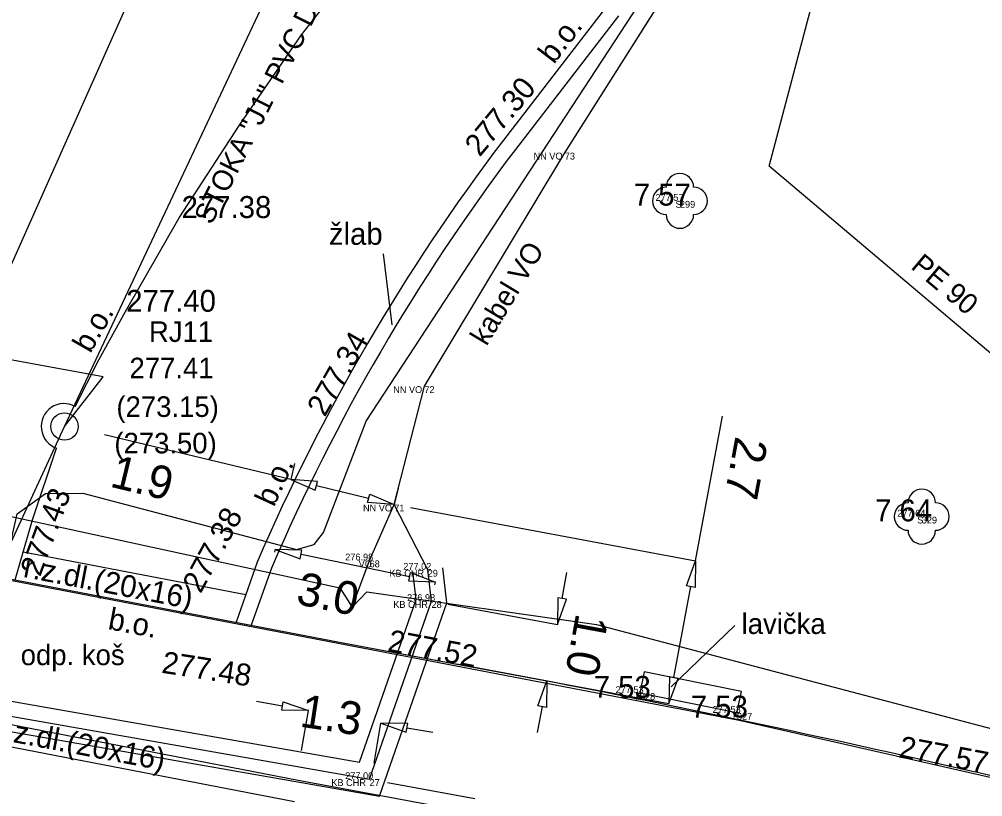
# Model space of a CAD drawing. Extents: x -601602 to -600882, y -1162594 to -1161950.
# Drawn here: x -601194.43 to -601176.86, y -1162080.85 to -1162066.67 of the extents above; entities that cross this region are included whole.
import ezdxf

# ---------------------------------------------------------------- set-up
doc = ezdxf.new("R2010")
doc.units = 0
for name, color, linetype in [('BODY', 7, 'Continuous'), ('BODY_CISLA', 7, 'Continuous'), ('BODY_KODY', 7, 'Continuous'), ('BODY_VYSKY_CELE', 7, 'Continuous'), ('G_POLOHOPIS', 7, 'Continuous'), ('G_TEXTY', 7, 'Continuous'), ('G_ZELEN', 7, 'Continuous'), ('G_ZNACKY', 7, 'Continuous'), ('H_KOTY_VYSKOVE', 7, 'Continuous'), ('H_VYSKY_PREVZATE', 7, 'Continuous'), ('IS_CHRÁNIČKY', 7, 'Continuous'), ('IS_EON_NN', 7, 'Continuous'), ('IS_KAN_JEDNOTNA', 7, 'Continuous'), ('IS_KAN_SPLASKOVA', 7, 'Continuous'), ('IS_PLYNOVOD', 7, 'Continuous'), ('IS_VO', 7, 'Continuous'), ('IS_VO_AREAL', 7, 'Continuous'), ('IS_VODOVOD', 7, 'Continuous'), ('KN_Hranice parcel', 7, 'Continuous'), ('VRSTVA 40', 7, 'Continuous'), ('Vrstva 49', 7, 'Continuous'), ('VRSTVA 5', 7, 'Continuous'), ('Vrstva 7', 7, 'Continuous')]:
    doc.layers.add(name, color=color, linetype=linetype)

# ---------------------------------------------------------------- blocks, each defined once
blk = doc.blocks.new('POINT_DISPLAY')
blk.add_line((0, 0), (0, 0))

msp = doc.modelspace()

# ---------------------------------------------------------------- linework, layer by layer
at = {"layer": 'G_POLOHOPIS'}
for p, q in [((-601183.03, -1162078.57), (-601183.11, -1162078.96)), ((-601181.26, -1162078.93), (-601183.03, -1162078.57)), ((-601181.34, -1162079.32), (-601183.11, -1162078.96)), ((-601181.34, -1162079.32), (-601181.26, -1162078.93))]:
    msp.add_line(p, q, dxfattribs=at)
at = {"layer": 'G_TEXTY'}
msp.add_line((-601181.38, -1162077.727), (-601182.54, -1162078.847), dxfattribs=at)
at = {"layer": 'G_ZELEN'}
for centre in [(-601182.38, -1162069.98), (-601177.97, -1162075.74)]:
    msp.add_circle(centre, 0.00025, dxfattribs=at)
for centre, start, end in [((-601182.38, -1162069.73), 0, 180), ((-601182.63, -1162069.98), 90, 270), ((-601182.13, -1162069.98), 270, 90), ((-601182.38, -1162070.23), 180, 360), ((-601177.97, -1162075.49), 0, 180), ((-601178.22, -1162075.74), 90, 270), ((-601177.72, -1162075.74), 270, 90), ((-601177.97, -1162075.99), 180, 360)]:
    msp.add_arc(centre, 0.25, start, end, dxfattribs=at)
at = {"layer": 'G_ZNACKY'}
msp.add_circle((-601193.603, -1162074.095), 0.25, dxfattribs=at)
at = {"layer": 'IS_CHRÁNIČKY'}
for points in [[(-601269.322, -1162072.054), (-601264.751, -1162067.079), (-601263.901, -1162066.729), (-601260.559, -1162067.068), (-601254.608, -1162068.26), (-601248.108, -1162069.46), (-601239.768, -1162071.15), (-601235.321, -1162071.969), (-601188.223, -1162080.219), (-601187.191, -1162077.25), (-601187.253, -1162076.744)], [(-601268.918, -1162072.426), (-601264.429, -1162067.541), (-601263.819, -1162067.291), (-601260.641, -1162067.612), (-601254.712, -1162068.8), (-601248.212, -1162070), (-601239.872, -1162071.69), (-601235.419, -1162072.511), (-601187.857, -1162080.841), (-601186.629, -1162077.31), (-601186.707, -1162076.676)]]:
    msp.add_lwpolyline(points, dxfattribs=at)
at = {"layer": 'IS_EON_NN'}
msp.add_lwpolyline([(-601195.29, -1162079.33), (-601194.47, -1162075.69), (-601193.95, -1162075.32), (-601193.27, -1162075.31), (-601189.37, -1162076.34), (-601189.05, -1162076.25), (-601188.88, -1162076.03), (-601188.1, -1162074), (-601182.8, -1162065.89), (-601180.73, -1162060), (-601180.49, -1162059.07), (-601180.33, -1162057.81), (-601181.56, -1162053.79), (-601182.34, -1162051.29), (-601183.48, -1162047.77), (-601184.72, -1162041.63), (-601184.91, -1162041.27)], dxfattribs=at)
at = {"layer": 'IS_KAN_JEDNOTNA'}
msp.add_line((-601197.971, -1162083.54), (-601193.603, -1162074.095), dxfattribs=at)
at = {"layer": 'IS_KAN_SPLASKOVA'}
for points in [[(-601193.603, -1162074.095), (-601184.326, -1162054.364)], [(-601193.603, -1162074.095), (-601192.9, -1162073.189), (-601219.294, -1162068.342)]]:
    msp.add_lwpolyline(points, dxfattribs=at)
at = {"layer": 'IS_PLYNOVOD'}
msp.add_lwpolyline([(-601188.62, -1162054.28), (-601187.94, -1162056.22), (-601196.32, -1162075.05)], dxfattribs=at)
at = {"layer": 'IS_VO'}
msp.add_lwpolyline([(-601221, -1162071.19), (-601220.94, -1162070.52), (-601220.15, -1162070.38), (-601205.25, -1162073.42), (-601205.07, -1162074.26), (-601204.715, -1162073.536), (-601188.58, -1162077.04), (-601188.36, -1162077.39), (-601188.09, -1162077.11), (-601183.9, -1162077.71), (-601173.92, -1162080.34), (-601173.63, -1162080.41), (-601159.1, -1162083.69), (-601159.12, -1162084.51), (-601158.666, -1162083.84), (-601145.3, -1162088.52)], dxfattribs=at)
at = {"layer": 'IS_VO_AREAL'}
msp.add_lwpolyline([(-601188.36, -1162077.39), (-601188.04, -1162076.54), (-601187.59, -1162075.52), (-601187.04, -1162073.36), (-601184.48, -1162069.1), (-601182.63, -1162066.18), (-601180.78, -1162062.19), (-601180.2, -1162059.82), (-601180.67, -1162056.17), (-601181.22, -1162052.64), (-601181.8, -1162050.4), (-601183.53, -1162045.99), (-601184.44, -1162042.4), (-601184.75, -1162039.81), (-601184.64, -1162038.31), (-601183.62, -1162036.02), (-601183.14, -1162034.73), (-601183.07, -1162033.56), (-601182.29, -1162031.84)], dxfattribs=at)
at = {"layer": 'IS_VODOVOD'}
msp.add_lwpolyline([(-601173.453, -1162076.323), (-601173.346, -1162075.998), (-601173.532, -1162075.454), (-601180.753, -1162069.349), (-601179.01, -1162062.743), (-601175.747, -1162061.656), (-601172.447, -1162060.451), (-601167.292, -1162058.586), (-601162.43, -1162056.641), (-601160.803, -1162054.849), (-601159.903, -1162053.41), (-601158.77, -1162051.508), (-601157.252, -1162048.634), (-601156.804, -1162047.317), (-601155.861, -1162044.019), (-601155.023, -1162041.098), (-601154.828, -1162039.298), (-601154.638, -1162035.819), (-601155.419, -1162031.331), (-601156.644, -1162026.466), (-601156.968, -1162024.813), (-601159.618, -1162011.435)], dxfattribs=at)
at = {"layer": 'KN_Hranice parcel'}
msp.add_lwpolyline([(-601156.16, -1162086.15), (-601160.29, -1162084.78), (-601165.08, -1162083.36), (-601173.19, -1162081.3), (-601181.3, -1162079.46), (-601222.59, -1162071.53)], dxfattribs=at)
at = {"layer": 'VRSTVA 40'}
for p, q in [((-601182.095, -1162076.544), (-601181.604, -1162073.909)), ((-601189.478, -1162075.064), (-601192.876, -1162074.245)), ((-601189.407, -1162074.773), (-601189.478, -1162075.064)), ((-601188.057, -1162075.407), (-601189.011, -1162075.177)), ((-601187.52, -1162075.228), (-601187.59, -1162075.52)), ((-601187.295, -1162075.575), (-601182.095, -1162076.544)), ((-601189.77, -1162076.386), (-601189.759, -1162076.337)), ((-601187.31, -1162076.84), (-601189.289, -1162076.433)), ((-601184.528, -1162077.234), (-601184.44, -1162076.762)), ((-601186.85, -1162076.986), (-601186.839, -1162076.937)), ((-601182.493, -1162078.678), (-601182.183, -1162077.016)), ((-601186.615, -1162077.335), (-601184.615, -1162077.706)), ((-601187.781, -1162078.181), (-601182.581, -1162079.15)), ((-601186.806, -1162078.363), (-601184.806, -1162078.734)), ((-601189.628, -1162079.196), (-601190.101, -1162079.113)), ((-601189.282, -1162080.008), (-601189.155, -1162079.278)), ((-601184.894, -1162079.206), (-601184.981, -1162079.678)), ((-601187.959, -1162080.239), (-601187.832, -1162079.509)), ((-601187.359, -1162079.592), (-601186.886, -1162079.674)), ((-601187.716, -1162080.589), (-601186.119, -1162080.885))]:
    msp.add_line(p, q, dxfattribs=at)
for points in [[(-601189.03, -1162075.255), (-601188.992, -1162075.099), (-601189.478, -1162075.064)], [(-601188.075, -1162075.485), (-601188.038, -1162075.329), (-601187.59, -1162075.52)], [(-601189.305, -1162076.512), (-601189.273, -1162076.355), (-601189.759, -1162076.337)], [(-601182.104, -1162077.031), (-601182.262, -1162077.001), (-601182.095, -1162076.544)], [(-601187.326, -1162076.919), (-601187.294, -1162076.762), (-601186.839, -1162076.937)], [(-601184.449, -1162077.248), (-601184.606, -1162077.219), (-601184.615, -1162077.706)], [(-601184.815, -1162079.221), (-601184.972, -1162079.191), (-601184.806, -1162078.734)], [(-601182.414, -1162078.693), (-601182.571, -1162078.664), (-601182.581, -1162079.15)], [(-601189.642, -1162079.274), (-601189.614, -1162079.117), (-601189.155, -1162079.278)], [(-601187.372, -1162079.67), (-601187.345, -1162079.513), (-601187.832, -1162079.509)]]:
    msp.add_lwpolyline(points, close=True, dxfattribs=at)
at = {"layer": 'Vrstva 49'}
msp.add_line((-601187.79, -1162070.947), (-601187.633, -1162072.239), dxfattribs=at)
at = {"layer": 'VRSTVA 5'}
for p, q in [((-601184.48, -1162069.1), (-601182.63, -1162066.18)), ((-601187.04, -1162073.36), (-601184.48, -1162069.1)), ((-601235.4, -1162072.236), (-601188.04, -1162080.53)), ((-601187.59, -1162075.52), (-601187.04, -1162073.36)), ((-601186.98, -1162076.71), (-601187.59, -1162075.52)), ((-601186.91, -1162077.28), (-601186.98, -1162076.71)), ((-601188.04, -1162080.53), (-601186.91, -1162077.28))]:
    msp.add_line(p, q, dxfattribs=at)
at = {"layer": 'Vrstva 7'}
for p, q in [((-601189.28, -1162066.95), (-601188.05, -1162065.37)), ((-601183.74, -1162066.46), (-601185.6, -1162068.87)), ((-601183.499, -1162066.603), (-601185.38, -1162069.04)), ((-601190.41, -1162068.6), (-601189.28, -1162066.95)), ((-601191.51, -1162070.29), (-601190.41, -1162068.6)), ((-601192.49, -1162072), (-601191.51, -1162070.29)), ((-601192.98, -1162072.88), (-601192.49, -1162072)), ((-601193.41, -1162073.73), (-601192.98, -1162072.88)), ((-601194.19, -1162075.8), (-601193.75, -1162074.49)), ((-601194.501, -1162076.895), (-601194.19, -1162075.8)), ((-601194.36, -1162076.38), (-601190.298, -1162077.163)), ((-601195.88, -1162076.63), (-601188.59, -1162078.03)), ((-601190.09, -1162076.57), (-601190.475, -1162077.668)), ((-601189.83, -1162076.68), (-601190.202, -1162077.72)), ((-601188.59, -1162078.03), (-601186.45, -1162078.43)), ((-601196.39, -1162079.18), (-601189.34, -1162080.55)), ((-601196.47, -1162079.57), (-601189.41, -1162080.94)), ((-601189.34, -1162080.55), (-601185.58, -1162081.25))]:
    msp.add_line(p, q, dxfattribs=at)
for centre, radius, start, end in [((-601156.293, -1162091.118), 36.795, 142.7959, 156.7097), ((-601156.303, -1162091.092), 36.493, 142.823, 156.7387), ((-601193.611, -1162074.096), 0.418, 61.2022, 250.5933), ((-601224.909, -1162286.548), 211.642, 76.95282, 79.53024), ((-601316.234, -1162688.106), 623.453, 76.572769, 77.107686)]:
    msp.add_arc(centre, radius, start, end, dxfattribs=at)

# ---------------------------------------------------------------- block references
at = {"layer": 'BODY'}
for p in [(-601184.48, -1162069.1), (-601182.38, -1162069.98), (-601187.04, -1162073.36), (-601187.59, -1162075.52), (-601177.97, -1162075.74), (-601188.04, -1162076.54), (-601186.98, -1162076.71), (-601186.91, -1162077.28), (-601183.11, -1162078.96), (-601181.34, -1162079.32), (-601188.04, -1162080.53)]:
    msp.add_blockref('POINT_DISPLAY', p, dxfattribs=at)

# ---------------------------------------------------------------- texts
at = {"layer": 'BODY_CISLA'}
for s, p in [('73', (-601184.48, -1162069.225)), ('299', (-601182.38, -1162070.105)), ('72', (-601187.04, -1162073.485)), ('71', (-601187.59, -1162075.645)), ('329', (-601177.97, -1162075.865)), ('68', (-601188.04, -1162076.665)), ('29', (-601186.98, -1162076.835)), ('28', (-601186.91, -1162077.405)), ('328', (-601183.11, -1162079.085)), ('327', (-601181.34, -1162079.445)), ('27', (-601188.04, -1162080.655))]:
    msp.add_text(s, height=0.125, dxfattribs=at).set_placement(p)
at = {"layer": 'BODY_KODY'}
for s, p in [('NN VO', (-601185.05, -1162069.225)), ('S', (-601182.461, -1162070.105)), ('NN VO', (-601187.61, -1162073.485)), ('NN VO', (-601188.16, -1162075.645)), ('S', (-601178.051, -1162075.865)), ('VO', (-601188.239, -1162076.665)), ('KB CHR', (-601187.678, -1162076.835)), ('KB CHR', (-601187.608, -1162077.405)), ('P', (-601183.186, -1162079.085)), ('P', (-601181.416, -1162079.445)), ('KB CHR', (-601188.738, -1162080.655))]:
    msp.add_text(s, height=0.125, dxfattribs=at).set_placement(p)
at = {"layer": 'BODY_VYSKY_CELE'}
for s, p in [('277.57 ', (-601182.825, -1162069.98)), ('277.64 ', (-601178.415, -1162075.74)), ('276.98 ', (-601188.485, -1162076.54)), ('277.02 ', (-601187.425, -1162076.71)), ('276.98 ', (-601187.355, -1162077.28)), ('277.53 ', (-601183.553, -1162078.96)), ('277.53 ', (-601181.783, -1162079.32)), ('277.00 ', (-601188.485, -1162080.53))]:
    msp.add_text(s, height=0.125, dxfattribs=at).set_placement(p)
at = {"layer": 'G_TEXTY'}
for s, p in [('lavička', (-601181.255, -1162077.881)), ('odp. koš', (-601194.403, -1162078.45))]:
    msp.add_text(s, height=0.375, dxfattribs=at).set_placement(p)
at = {"layer": 'H_KOTY_VYSKOVE'}
for s, p in [(' 7 57', (-601183.37, -1162070.066)), (' 7 64', (-601178.97, -1162075.826)), (' 7 53', (-601184.101, -1162079.046)), (' 7 53', (-601182.331, -1162079.406))]:
    msp.add_text(s, height=0.4, dxfattribs=at).set_placement(p)
at = {"layer": 'H_VYSKY_PREVZATE'}
for s, rotation, p in [('277.30 ', 50.2089, (-601186.031, -1162069.191)), ('277.34 ', 60.1243, (-601188.857, -1162073.937)), ('277.43 ', 69.7516, (-601194.048, -1162076.851)), ('277.38 ', 61.6357, (-601191.121, -1162077.157)), ('277.52 ', 349.3397, (-601187.727, -1162078.19)), ('277.48 ', 351.0894, (-601191.847, -1162078.587)), ('277.57 ', 349.3397, (-601178.407, -1162080.13))]:
    msp.add_text(s, height=0.4, rotation=rotation, dxfattribs=at).set_placement(p)
for s, p in [('277.38', (-601191.468, -1162070.292)), ('277.40', (-601192.478, -1162072.003))]:
    msp.add_text(s, height=0.4, dxfattribs=at).set_placement(p)
at = {"layer": 'IS_KAN_JEDNOTNA'}
for s, p in [('RJ11', (-601192.064, -1162072.553)), ('277.41', (-601192.419, -1162073.216)), ('(273.15)', (-601192.657, -1162073.921)), ('(273.50)', (-601192.695, -1162074.586))]:
    msp.add_text(s, height=0.375, dxfattribs=at).set_placement(p)
at = {"layer": 'IS_KAN_SPLASKOVA'}
msp.add_text('STOKA "J1" PVC DN200 dl.=21.8m', height=0.375, rotation=63.3962, dxfattribs=at).set_placement((-601190.923, -1162070.432))
at = {"layer": 'IS_VO_AREAL'}
msp.add_text('kabel VO', height=0.375, rotation=58.9967, dxfattribs=at).set_placement((-601185.907, -1162072.642))
at = {"layer": 'IS_VODOVOD'}
msp.add_text('PE 90', height=0.375, rotation=319.7871, dxfattribs=at).set_placement((-601178.187, -1162071.201))
at = {"layer": 'VRSTVA 40'}
for s, rotation, p in [('2.7', 259.4436, (-601181.364, -1162074.259)), ('1.9', 346.4379, (-601192.795, -1162075.19)), ('3.0', 348.3885, (-601189.402, -1162077.329)), ('1.0', 259.491, (-601184.27, -1162077.488)), ('1.3', 351.3057, (-601189.33, -1162079.569))]:
    msp.add_text(s, height=0.6, rotation=rotation, dxfattribs=at).set_placement(p)
at = {"layer": 'Vrstva 49'}
for s, rotation, p in [('b.o.', 52.3396, (-601184.68, -1162067.499)), ('b.o.', 60.183, (-601193.132, -1162072.776)), ('b.o.', 65.1591, (-601189.785, -1162075.578)), ('r.z.dl.(20x16)', 349.0821, (-601194.372, -1162076.838)), ('b.o.', 349.129, (-601192.828, -1162077.789)), ('r.z.dl.(20x16)', 349.242, (-601194.875, -1162079.792))]:
    msp.add_text(s, height=0.4, rotation=rotation, dxfattribs=at).set_placement(p)
msp.add_text('žlab', height=0.4, dxfattribs=at).set_placement((-601188.782, -1162070.781))

doc.saveas('drawing.dxf')
